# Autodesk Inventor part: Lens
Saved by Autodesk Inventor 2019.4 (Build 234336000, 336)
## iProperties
Created: 2020-09
Part Number: Lens
Material: Generic
Document SubType Name: Modeling
Designer: Administrator
Density: 1 g/cm^3
Appearance: Default
Title: Lens
Author: Administrator
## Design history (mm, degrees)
feature "Body1"
body "Solid1"
